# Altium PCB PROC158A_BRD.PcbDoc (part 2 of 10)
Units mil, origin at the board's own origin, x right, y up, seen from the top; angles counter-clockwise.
Board outline 3346.45 x 4921.26 mil, 8 copper layers (Top Layer, GND1, SIG1, PWR1, PWR2, SIG2, GND2, Bottom Layer), stack 54.534 mil thick; 718 components, 459 nets, 2307 pads, 1179 vias.
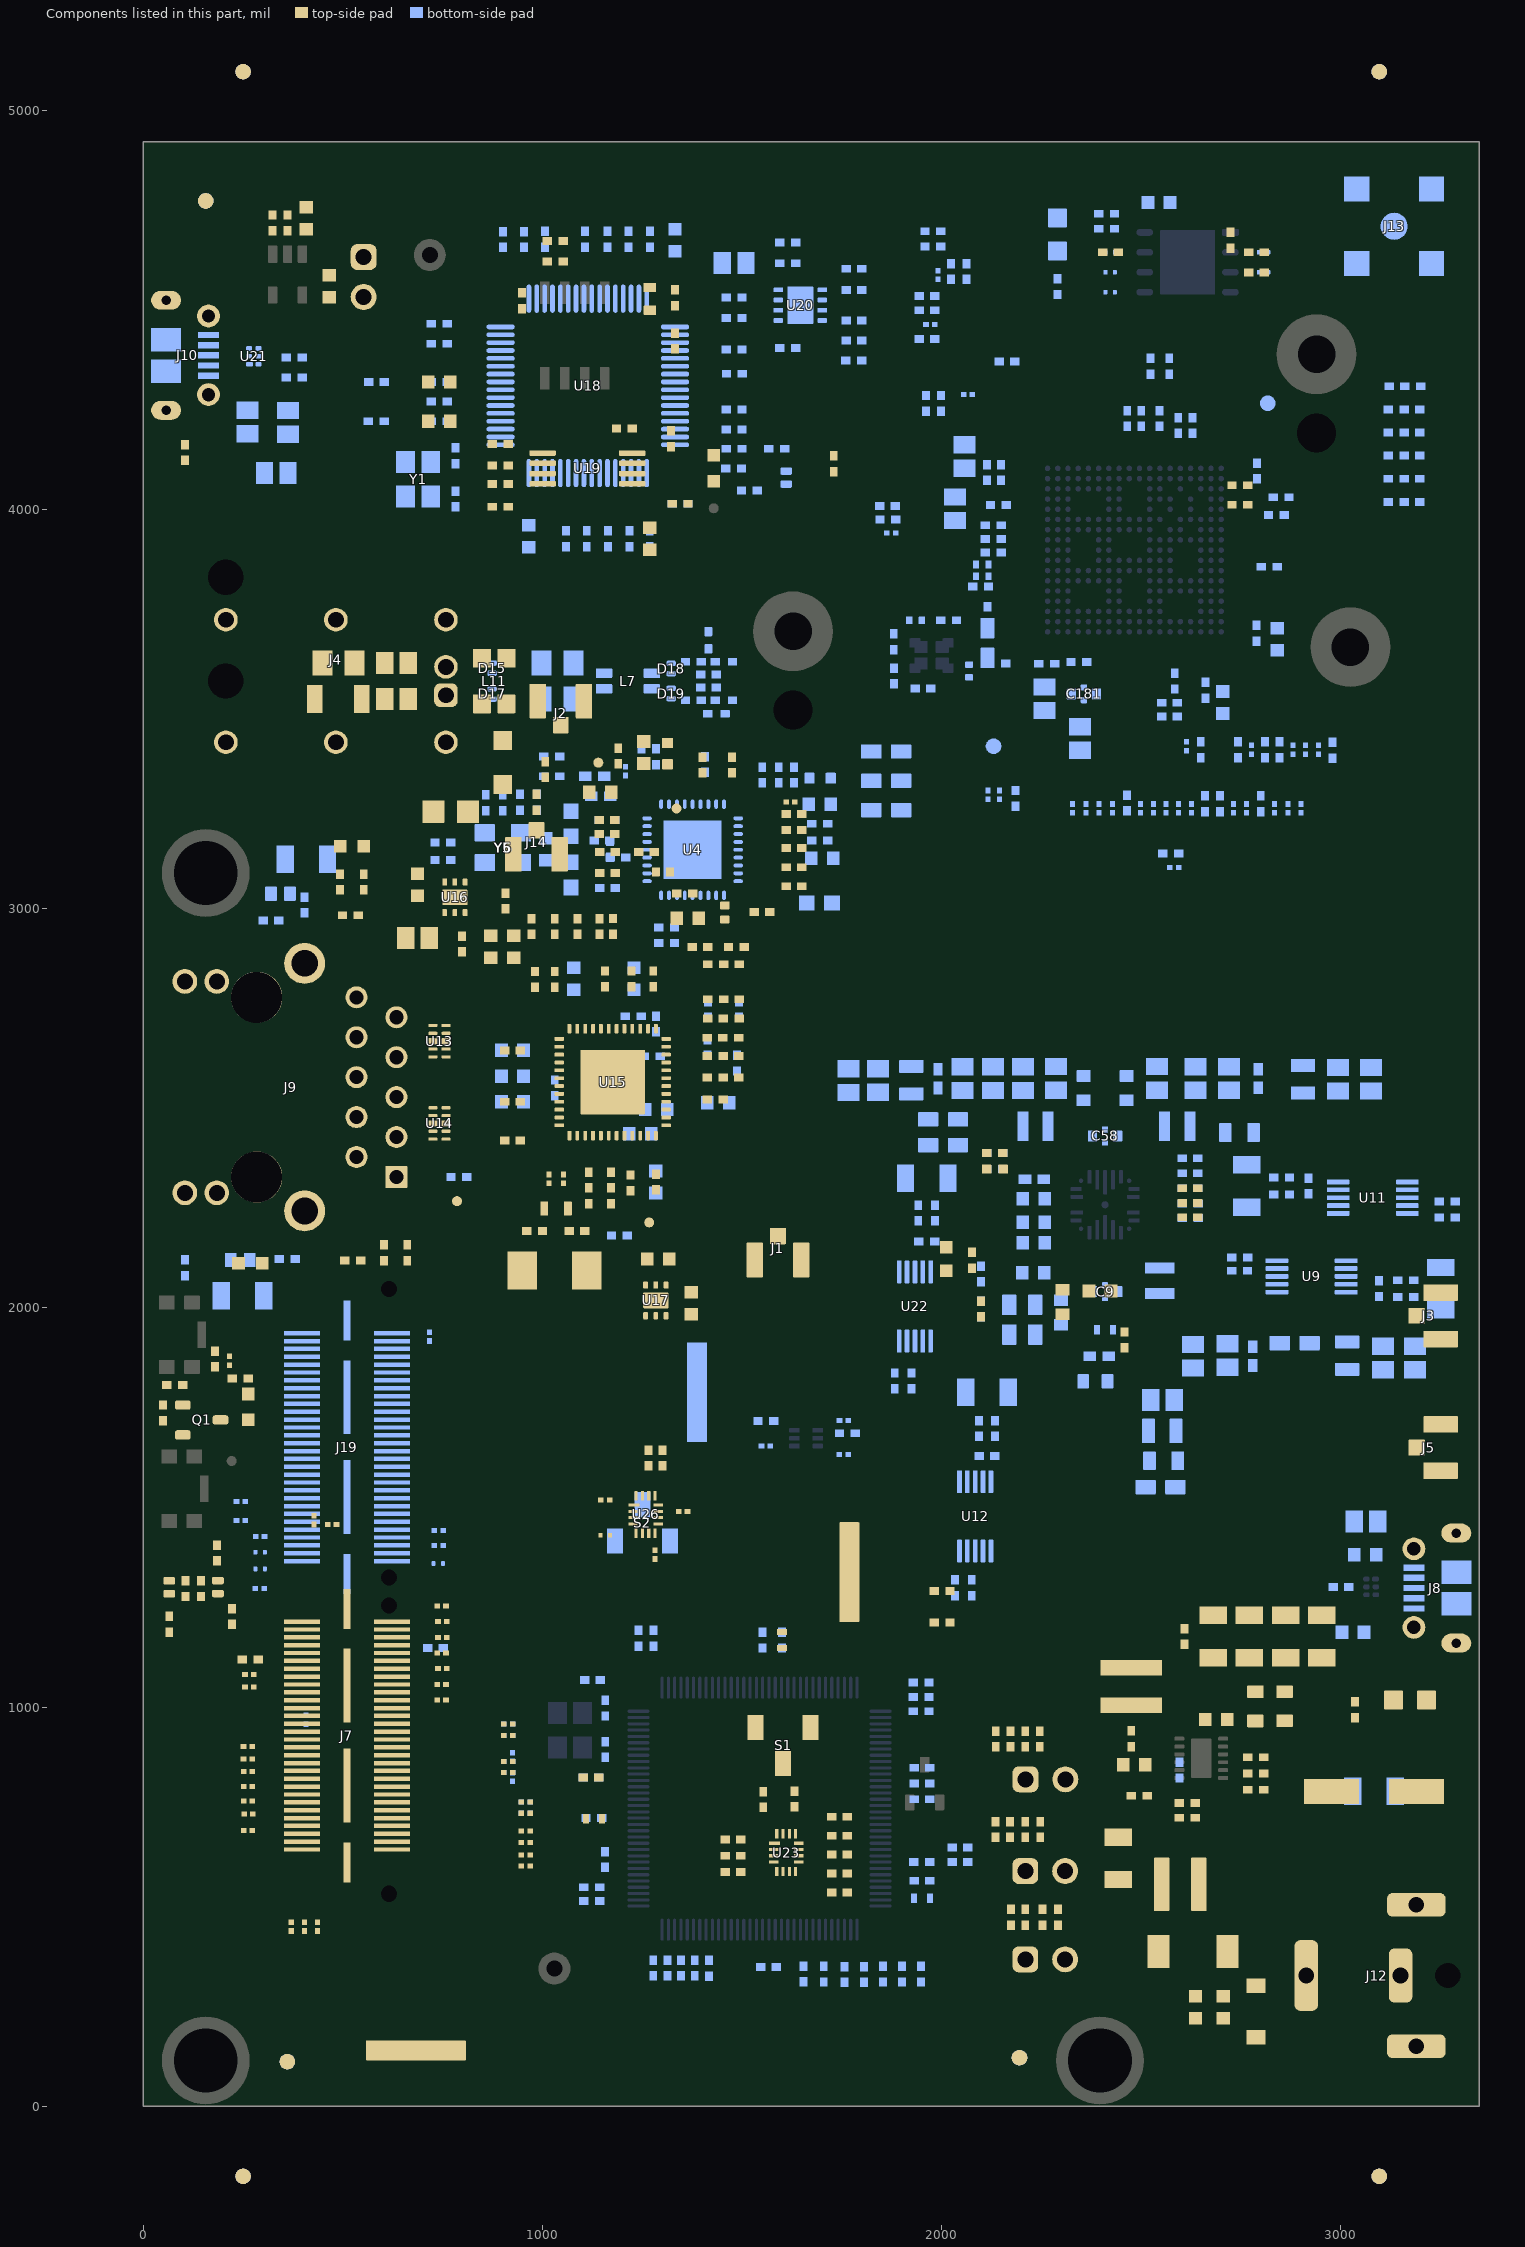
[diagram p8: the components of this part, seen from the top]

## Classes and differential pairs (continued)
component class PROC158A_JTAG_EMU_Connector: C98 J19 R72 R196 R226 R243 R244 R296 R321 R353 R354 R355 R356 R357 R358 R359 R360 R374 R375 R376 R503 R508 R512 S1 U23
component class PROC158A_Auto_Ethernet_PHY: C8 C11 C12 C13 C16 C20 C24 C32 C35 C36 C37 C40 C44 C46 C52 C54 C95 C121 C172 D10 D14 FB1 FB2 FB3 R6 R11 R12 R13 R15 R16 R34 R46 R50 R61 R63 R74 R75 R76 R77 R78 R79 R88 R89 R93 R96 R100 R168 R176 R177 R178 R185 R186 R225 R230 R234 R237 R238 R239 R240 R241 R242 R245 R246 R247 R248 R249 R251 R252 R253 R254 R255 R256 R257 R258 R350 TP2 TP3 U4 Y5 Y6
component class PROC158A_FTDI: C68 C69 C72 C73 C77 C78 C79 C82 C83 C84 C86 C87 C88 C89 C90 C91 D1 L3 L4 R131 R144 R145 R146 R147 R148 R149 R150 R151 R153 R157 R158 R162 R163 R166 R169 R170 R171 R179 R180 R181 R184 R187 R201 R205 R330 U18 U19 Y1
component class PROC158A_FTDI_PWR: C39 C85 C93 C94 C97 J10 R73 R182 R183 R202 R203 R204 R206 R207 R208 R209 U20 U21
component class PROC158A_Ethernet_PWR: C34 C38 C48 C53 C56 C57 C59 C60 C65 C158 C159 C160 C183 C184 C185 C186 C187 C188 C189 C190 C191 C192 C193 R293 R294 R295 U16 U17
component class PROC158A_Ethernet_PHY: C30 C33 D7 D8 m R92 R97 R98 R101 R103 R105 R108 R112 R113 R117 R118 R120 R121 R122 R132 R137 R139 R141 R142 R143 R173 R195 R211 R286 R287 R288 R289 R290 R325 R336 R337 R338 R339 R340 R342 R344 R369 R370 R413 R414 TP5 U15 Y4
component class PROC158A_Ethernet_Magnetics: C27 C28 J9 R68 R69 R119 R130 R400 R401 R419 TP6 U13 U14
component class PROC158A_Debug_Connector: C18 J7 R5 R51 R80 R81 R82 R84 R90 R91 R94 R114 R115 R135 R138 R160 R164 R167 R188 R197 R198 R215 R223 R283 R320 R322 R323 R324 R327 R328 R329 R341 R345 R349 R351 R361 R363 R364 R365 R366 R371 R377 R379 R390 R391 R399 R418 R422 R423 R424 R425 S2 U26
component class PROC158A_Current_Sensors: C14 C17 C19 C81 R26 R27 R29 R30 R32 R33 R35 R47 R56 R57 R58 R59 R60 R62 R64 R65 R66 R346 R348 R352 U9 U11 U12 U22
component class Header: J17 J18 J20 J21 J22 J23 P1
component class Logo: Logo1
component class PROC158A_Hardware: "CAUTION HOT SURFACE1" "ESD Susceptible1" FID1 FID2 FID3 FID4 FID5 FID6 FID7 FID8 FID9 FID10 FID11 FID12 FID13 FID14 FID15 FID16 LBL1 Logo1 LOGO2 Logo3 Logo4 Logo5 ZZ1 ZZ2 ZZ3 ZZ4
component class FiducialMark: FID1 FID2 FID3 FID4 FID5 FID6 FID7 FID8 FID9 FID10 FID11 FID12 FID13 FID14 FID15 FID16
component class AssemblyNote: ZZ1 ZZ2 ZZ3 ZZ4
component class Label: LBL1
differential pair TX4: +TX4_P -TX4_N
differential pair TX2_CLK: +TX2_CLK_P -TX2_CLK_N
differential pair CSI2_TX4_LVDS_CLK: +CSI2_TX4_LVDS_CLK_P -CSI2_TX4_LVDS_CLK_N
differential pair CSI2_TX2_CLK_LVDS_FRCLK: +CSI2_TX2_CLK_LVDS_FRCLK_P -CSI2_TX2_CLK_LVDS_FRCLK_N
differential pair FRCLK: +FRCLK_P -FRCLK_N
differential pair CSI2_TX3: +CSI2_TX3_P -CSI2_TX3_N
differential pair CSI2_TX1_LVDS_TX1: +CSI2_TX1_LVDS_TX1_P -CSI2_TX1_LVDS_TX1_N
differential pair CSI2_TX0_LVDS_TX0: +CSI2_TX0_LVDS_TX0_P -CSI2_TX0_LVDS_TX0_N
differential pair TX3: +TX3_P -TX3_N
differential pair TX1: +TX1_P -TX1_N
differential pair TX0: +TX0_P -TX0_N
differential pair TRD3: +TRD3_P -TRD3_N
differential pair TRD2: +TRD2_P -TRD2_N
differential pair TRD1: +TRD1_P -TRD1_N
differential pair ETH_TRD: +ETH_TRD_P -ETH_TRD_N
differential pair FTDI_USBD: +FTDI_USBD_P -FTDI_USBD_N
differential pair XDSET_1_D: +XDSET_1_D_P -XDSET_1_D_N
differential pair ETH_TD_4: +TD_4_P -TD_4_N
differential pair ETH_TD_3: +TD_3_P -TD_3_N
differential pair ETH_TD_2: +TD_2_P -TD_2_N
differential pair ETH_TD_1: +TD_1_P -TD_1_N

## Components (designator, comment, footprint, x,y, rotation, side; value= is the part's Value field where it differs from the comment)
C1 "GCM188R71C105KA64D" 0603L 2544.56,4769 r180 bottom value=1uF
C2 "CGA2B3X7R1H104K050BB" 0402L 2413.32,4741 r0 bottom value=0.1uF
C3 "GCM188R70J225KE22D" 0603L 2230.57,2273.47 r0 bottom value=2.2uF
C4 "C0805C106J8RACAUTO" 0805L 1840.13,2569.34 r90 bottom value=10uF
C5 "GCM155R71C224KE02D" 0402L 2149,4092.84 r270 bottom value=0.22uF
C6 "GCJ188C70J475KE02J" FP-GCJ188C70J475KE02J_0603-MFG 2385.11,1816.11 r0 bottom value=4.7µF
C7 "GCM21BR71A106KE22L" 0805L 2540,2575 r90 bottom value=10uF
C8 "GCM188R70J225KE22D" 0603L 1694.56,3261.81 r180 bottom value=2.2uF
C9 "NFM18HC105C1C3D" FP-NFM18HC105C1C3D_0603-MFG 2409.48,2040.61 r180 bottom
C10 "GCM188R71C105KA64D" 0603L 2481.98,855.36 r180 top value=1uF
C11 "GCM188R70J225KE22D" 0603L 1144.56,3292 r180 top value=2.2uF
C12 "GCM155R71C104KA55D" 0402L 1023.32,3380.81 r0 bottom value=0.1uF
C13 "GCM155R71C104KA55D" 0402L 1630,3334.81 r270 bottom value=0.1uF
C14 "GCM155R71A104KA55D" 0402L 3095.21,2048.23 r90 bottom value=0.1uF
C15 "GCM21BR71A106KE22L" 0805L 2286,2575 r90 bottom value=10uF
C16 "CGA2B3X7R1H103K050BB" 0402L 1023.32,3331.81 r180 bottom value=0.01uF
C17 "GCM155R71A104KA55D" 0402L 2919.04,2305.44 r270 bottom value=0.1uF
C18 "C0402C104K8RACTU" 0402L 1266.05,1623.71 r270 top value=0.1uF
C19 "GCM155R71A104KA55D" 0402L 2113.62,1628.99 r180 bottom value=0.1uF
C20 "CGA2B3X7R1H103K050BB" 0402L 1592,3334.81 r90 bottom value=0.01uF
C21 "GCM155R71C224KE02D" 0402L 2475,920.74 r90 top value=0.22uF
C22 "GCM155R71C224KE02D" 0402L 2608.2,1176.7 r90 top value=0.22uF
C23 "GCM31CR71A226KE02L" 1206_180L 2952,1176.7 r270 top value=22uF
C24 "GCM188R70J225KE22D" 0603L 1254,3391.25 r270 top value=2.2uF
C25 "GCM31CR71A226KE02L" 1206_180L 2770.83,1176.7 r270 top value=22uF
C26 "GCM31CR71A226KE02L" 1206_180L 2861.42,1176.7 r270 top value=22uF
C27 "C0603C104K4RACAUTO" FP-C0603C104K4RACAUTO_0603-MFG 243.02,2119.9 r0 bottom
C28 "C0603C104K4RACAUTO" FP-C0603C104K4RACAUTO_0603-MFG 343.71,3037.47 r0 bottom
C29 "GCM31CR71A226KE02L" 1206_180L 2680.25,1176.7 r270 top value=22uF
C30 "GCM1555C1H270JA16D" 0402L 1086.42,2192.39 r0 top value=27pF
C31 "GCM21BR71A106KE22L" 0805L 2553.15,1769.45 r0 bottom value=10uF
C32 "GCM188R70J225KE22D" 0603L 1364.39,2976.15 r180 top value=2.2uF
C33 "GCM1555C1H270JA16D" 0402L 980.44,2192.39 r180 top value=27pF
C34 "GCM155R71H102KA37D" 0402L 798.3,2911.52 r90 top value=1000pF
C35 "GCM188R70J225KE22D" 0603L 1700.79,3125.98 r180 bottom value=2.2uF
C36 "GCM155R71C104KA55D" 0402L 1694.5,3171.06 r180 bottom value=0.1uF
C37 "CGA2B3X7R1H103K050BB" 0402L 1311.02,2952.76 r180 bottom value=0.01uF
C38 "CGA4J3X7R1H225K125AB" 0805L 687.02,2927.1 r180 top value=2.2uF
C39 "CL21B106KOQNNNE" 0805L 333.24,4091.18 r180 bottom value=10uF
C40 "GRM155R71E473KA88D" 0402 1146.38,3281.81 r180 bottom value=0.047uF
C41 "GCM155C71A105KE38D" 0402_070 1951,520.81 r0 bottom value=1uF
C42 "C0402C104K8RACTU" 0402L 1128.69,722.02 r0 bottom value=0.1uF
C43 "C0402C104K8RACTU" 0402L 1551.66,1167.61 r270 bottom value=0.1uF
C44 "CGA2B3X7R1H103K050BB" 0402L 1694.5,3212.75 r0 bottom value=0.01uF
C45 "CL21B106KOQNNNE" 0805L 3062.92,1465.35 r0 bottom value=10uF
C46 "GCM155R71C104KA55D" 0402L 1311.02,2914.18 r0 bottom value=0.1uF
C47 "C0402C104K8RACTU" 0402L 949.01,4522.91 r90 top value=0.1uF
C48 "GCM188R71C105KA64D" 0603L 687.02,3059.84 r270 top value=1uF
C49 "C0402C104K8RACTU" 0402L 1123.53,548.54 r180 bottom value=0.1uF
C50 "C0402C103K4RACTU" 0402L 1566.45,349.16 r180 bottom value=0.01uF
C51 "GCM188R70J225KE22D" 0603L 2396.65,2042.31 r180 top value=2.2uF
C52 "CGA2B3X7R1H103K050BB" 0402L 1284.68,3380.79 r90 bottom value=0.01uF
C53 "GCM188R71C105KA64D" 0603L 1229.16,2824.15 r90 bottom value=1uF
C54 "GCM155R71C104KA55D" 0402L 1248.1,3380.79 r270 bottom value=0.1uF
C55 "GCM155R71C224KE02D" 0402L 2097.72,3807.08 r0 bottom value=0.22uF
C56 "GCM188R71C105KA64D" 0603L 925.03,2580.19 r180 bottom value=1uF
C57 "GCM155R71A104KA55D" 0402L 1030.83,2551.1 r270 bottom value=0.1uF
C58 "NFM18HC105C1C3D" FP-NFM18HC105C1C3D_0603-MFG 2409.48,2430.63 r180 bottom
C59 "GCM188R71C105KA64D" 0603L 925.03,2516.33 r180 bottom value=1uF
C60 "GCM188R71C105KA64D" 0603L 1373.01,2012.02 r90 top value=1uF
C61 "GCM155C71A105KE38D" 0402_070 1129.01,720.62 r180 top value=1uF
C62 "GCM155C71A105KE38D" 0402_070 1600.04,1167.93 r90 top value=1uF
C63 "GCM1555C1H8R0DA16D" 0402L 1157.31,997.36 r270 bottom
C64 "C0402C104K8RACTU" 0402L 1600.44,1167.61 r270 bottom value=0.1uF
C65 "GCM188R71C105KA64D" 0603L 1290.01,2122.43 r180 top value=1uF
C66 "C0402C103K4RACTU" 0402L 1950.58,848.1 r180 bottom value=0.01uF
C67 "C0402C104K8RACTU" 0402L 1950.58,808.77 r180 bottom value=0.1uF
C68 "C1608X7S1A475K080AC" 0603L 741.44,4221.1 r180 top value=4.7uF
C69 "C0402C104K8RACTU" 0402L 741.44,4221.1 r0 bottom value=0.1uF
C70 "GCM1555C1H8R0DA16D" 0402L 1157.31,893.56 r270 bottom
C71 "C0402C104K8RACTU" 0402L 1240.63,1172.52 r270 bottom value=0.1uF
C72 "C1608X7S1A475K080AC" 0603L 741.44,4319.53 r180 top value=4.7uF
C73 "C0402C104K8RACTU" 0402L 741.44,4319.53 r0 bottom value=0.1uF
C74 "C1005X7S1A225K050BC" 0402_065L 1121.58,823.24 r0 top value=2.2uF
C75 "C0402C104K8RACTU" 0402L 1121.58,823.24 r0 bottom value=0.1uF
C76 "C0402C104K8RACTU" 0402L 1950.94,564.81 r180 bottom value=0.1uF
C77 "C0402C104K8RACTU" 0402L 1345,4014.41 r0 bottom value=0.1uF
C78 "C0402C104K8RACTU" 0402L 1345,4014.41 r0 top value=0.1uF
C79 "C1608X7S1A475K080AC" 0603L 965.97,3932.47 r270 bottom value=4.7uF
C80 "GCJ188C70J475KE02J" FP-GCJ188C70J475KE02J_0603-MFG 2303.15,2014.75 r90 top value=4.7µF
C81 "GCM155R71A104KA55D" 0402L 1962.59,2166.46 r180 bottom value=0.1uF
C82 "C0402C104K8RACTU" 0402L 1480.12,4400.69 r0 bottom value=0.1uF
C83 "GCM1555C1H8R0DA16D" 0402L 782.36,4134.49 r90 bottom
C84 "GCM1555C1H8R0DA16D" 0402L 782.36,4026.22 r270 bottom
C85 "C1005X7S1A225K050BC" 0402_065L 1614.4,4404.56 r0 bottom value=2.2uF
C86 "C0402C104K8RACTU" 0402L 1205.15,4202.72 r180 top value=0.1uF
C87 "GCM188R71C105KA64D" 0603L 1332.18,4674.04 r90 bottom value=1uF
C88 "C0402C104K8RACTU" 0402L 1269.17,4677.01 r90 bottom value=0.1uF
C89 "C0402C104K8RACTU" 0402L 1480.12,4250.39 r0 bottom value=0.1uF
C90 "GCM188R71C105KA64D" 0603L 1268.76,3926.57 r270 top value=1uF
C91 "C0402C104K8RACTU" 0402L 1268.76,3926.57 r270 bottom value=0.1uF
C92 "GCM155R71C224KE02D" 0402L 2592.82,4210.19 r270 bottom value=0.22uF
C93 "04025A150FAT2A" 0402L 1614.4,4617.01 r0 bottom value=15pF
C94 "C1005X7S1A225K050BC" 0402_065L 1614.4,4668.86 r0 bottom value=2.2uF
C95 "CGA3E2C0G1H220J080AA" 0603 1072,3084.81 r270 bottom value=22pF
C96 "GCM155R71C224KE02D" 0402L 2789,3690 r90 bottom value=0.22uF
C97 "C0402C104K8RACTU" 0402L 378.25,4330.82 r0 bottom value=0.1uF
C98 "C0402C104K8RACTU" 0402L 1631.35,769.51 r270 top value=0.1uF
C99 "EEHZC1V680XP" SM_RADIAL_6.3BMM 3082.94,788.8 r0 top value=68uF
C100 "C3216X7R1H475K160AC" 1206_180L 2442,621 r90 top value=4.7uF
C101 "C3216X7R1H475K160AC" 1206_180L 3082.94,788.8 r0 bottom value=4.7uF
C102 "GRT155R70J105KE01D" FP-GRT155R70J105KE01D_0402-MFG 2101.66,3862.19 r180 bottom
C103 "GRT155R70J105KE01D" FP-GRT155R70J105KE01D_0402-MFG 2101.66,3832.66 r180 bottom
C104 "CGA3E3X8R1H104K080AB" 0603L 2705.05,248.05 r270 top value=0.1uF
C105 "GCM155R71C104KA55D" 0402L 105.96,1296.65 r90 top value=0.1uF
C106 "GCM1555C1H3R9BA16D" FP-GCM1555C1H3R9BA16D_0402-MFG 1934.63,3722.51 r180 bottom value=3.9pF
C107 "GCM155R71C224KE02D" 0402L 2129.27,3960.48 r0 bottom value=0.22uF
C108 "GCM1555C1H3R9BA16D" FP-GCM1555C1H3R9BA16D_0402-MFG 2068.85,3595.44 r270 bottom value=3.9pF
C109 "C0402C103K4RACTU" 0402L 1948.63,1025.56 r180 bottom value=0.01uF
C110 "GCM21BR71A106KE22L" 0805L 2257.86,3525.98 r270 bottom value=10uF
C111 "GCM155R71C224KE02D" 0402L 2129.27,3892.34 r0 bottom value=0.22uF
C112 "GCM21BR71A106KE22L" 0805L 2057,4132.53 r90 bottom value=10uF
C113 "GCM155R71C224KE02D" 0402L 2114,4092.84 r270 bottom value=0.22uF
C114 "GCM21BR71A106KE22L" 0805L 2033.6,4001.8 r270 bottom value=10uF
C115 "GCM155R71C224KE02D" 0402L 2142.12,4011.14 r0 bottom value=0.22uF
C116 "GCM21BR71A106KE22L" 0805L 2347,3426.47 r270 bottom value=10uF
C117 "GCM155R71C224KE02D" 0402L 2343.69,3618 r180 bottom value=0.22uF
C118 "CGA4J1X7R1H475K125AC" FP-CGA4J1X7R1H475K125AC_0805-MFG 2786.07,1001.58 r270 top value=4.7µF
C119 "GCM155R71C224KE02D" 0402 2793.46,2574.68 r90 bottom value=0.22uF
C120 "GCM155R71C224KE02D" 0402 1990.96,2574.38 r90 bottom value=0.22uF
C121 "CGA3E2C0G1H220J080AA" 0603 1071.93,3212.81 r90 bottom value=22pF
C122 "GCM155R71C224KE02D" 0402 2779.53,1879.19 r270 bottom value=0.22uF
C123 "GCM188R70J225KE22D" 0603L 2230.89,2214.34 r0 bottom value=2.2uF
C124 "GCM21BR71A106KE22L" 0805L 2203.5,2574.34 r90 bottom value=10uF
C125 "GCM21BR71A106KE22L" 0805L 2719.81,2574.81 r90 bottom value=10uF
C126 "CGA3E3X8R1H104K080AB" 0603L 2635.95,248.44 r270 top value=0.1uF
C127 "GCM21BR71A106KE22L" 0805L 2635.32,2574.81 r90 bottom value=10uF
C128 "CGA4J1X7T0J226M" 0805_155 3015.86,1880.36 r270 bottom value=22uF
C129 "GCM21BR71A106KE22L" 0805L 2715.81,1880.94 r270 bottom value=10uF
C130 "GCM21BR71A106KE22L" 0805L 2629.81,1878.94 r270 bottom value=10uF
C131 "GCM155R71C104KA55D" 0402L 1998.62,4265.88 r90 bottom value=0.1uF
C132 "GCM21BR71A106KE22L" 0805L 2052.83,2574.34 r90 bottom value=10uF
C133 "C0402C104K8RACTU" 0402L 1763.74,1685.81 r0 bottom value=0.1uF
C134 "GCM21BR71A106KE22L" 0805L 2128.17,2574.34 r90 bottom value=10uF
C135 "GCM155R71C104KA55D" 0402L 1865.22,3974.81 r0 bottom value=0.1uF
C136 "GCM155R71C104KA55D" 0402L 2062.61,4596.13 r270 bottom value=0.1uF
C137 "GCM188R70J225KE22D" 0603L 2704,3516.44 r90 bottom value=2.2uF
C138 "GCM155R71C224KE02D" 0402L 2747,4012 r180 top value=0.22uF
C139 "GCM155R71C224KE02D" 0402L 2661,3547.32 r90 bottom value=0.22uF
C140 "GCM155R71C224KE02D" 0402L 2464.86,4228.19 r270 bottom value=0.22uF
C141 "GCM155R71C224KE02D" 0402L 2628.47,4210.19 r270 bottom value=0.22uF
C142 "GCM155R71C224KE02D" 0402L 2747,4060.87 r180 top value=0.22uF
C143 "CGA4J1X7T0J226M" 0805_155 2552.66,1692.06 r0 bottom value=22uF
C144 "GCJ188C70J475KE02J" FP-GCJ188C70J475KE02J_0603-MFG 2463.29,2550.43 r270 bottom value=4.7µF
C145 "GCM188R71C105KA64D" 0603L 408.44,4729.82 r90 top value=1uF
C146 "GCM188R70J225KE22D" 0603L 2841,3675.44 r90 bottom value=2.2uF
C147 "GCJ188C70J475KE02J" FP-GCJ188C70J475KE02J_0603-MFG 2299.36,1988.38 r90 bottom value=4.7µF
C148 "GCM188R70J225KE22D" 0603L 2230.89,2163.42 r0 bottom value=2.2uF
C149 "GCM188R70J225KE22D" 0603L 466.12,4559.69 r270 top value=2.2uF
C150 "GCM155R71C104KA55D" 0402L 2838.54,3986.51 r180 bottom value=0.1uF
C151 "CGA4J1X7T0J226M" 0805_155 1924.06,2570.34 r90 bottom value=22uF
C152 "C0805C106J8RACAUTO" 0805L 1767,2569.26 r90 bottom value=10uF
C153 "GCJ188C70J475KE02J" FP-GCJ188C70J475KE02J_0603-MFG 2355.67,2550.43 r270 bottom value=4.7µF
C154 "C0805C106J8RACAUTO" 0805L 3105.86,1874.28 r270 bottom value=10uF
C155 "KGM05ACG1H470FH" FP-KGM05ACG1H470FH_0402-MFG 1415.62,3672.6 r270 bottom value=47pF
C156 "KGM05ACG1H220FH" FP-KGM05ACG1H220FH_0402-MFG 1454.38,3618.51 r0 bottom value=22pF
C157 "CGA4J2X7R2A104K125AA" 0805_HV 1037.67,3615.54 r0 bottom value=0.1uF
C158 "GCM155R71A104KA55D" 0402L 1432.69,2522.05 r0 top value=0.1uF
C159 "GCM188R71C105KA64D" 0603L 1078.54,2824.03 r90 bottom value=1uF
C160 "GCM155R71A104KA55D" 0402L 1156.91,2824.15 r90 top value=0.1uF
C161 "CGA4J2X7R2A104K125AA" 0805_HV 1037.67,3524.99 r0 bottom value=0.1uF
C162 "KGM05ACG1H220FH" FP-KGM05ACG1H220FH_0402-MFG 1454.38,3522.02 r180 bottom value=22pF
C163 "GCM155R71C224KE02D" 0402L 2500.01,4228.19 r270 bottom value=0.22uF
C164 "GCM155R71C224KE02D" 0402L 2584,3570 r90 bottom value=0.22uF
C165 "GCM155R71C224KE02D" 0402L 2789.81,4096.45 r270 bottom value=0.22uF
C166 "KGM05ACG1H470FH" FP-KGM05ACG1H470FH_0402-MFG 1435.86,3488.17 r0 bottom value=47pF
C167 "CC1206KKX7RCBB472" FP-CC1206KKX7RCBB472_1206-MFG 488.5,3525.09 r180 top value=4.7nF
C168 "GCM155R71C224KE02D" 0402L 2263.21,3613.51 r0 bottom value=0.22uF
C169 "CGA4J1X7T0J226M" 0805_155 2905.34,2572.81 r90 bottom value=22uF
C170 "GCM155R71C224KE02D" 0402L 2820.54,3856.66 r180 bottom value=0.22uF
C171 "GCM188R70J225KE22D" 0603L 2230,2088 r0 bottom value=2.2uF
C172 "GCM155R71C104KA55D" 0402L 750.45,3166.22 r0 bottom value=0.1uF
C173 "CGA4J1X7R1H475K125AC" FP-CGA4J1X7R1H475K125AC_0805-MFG 2859,1001.72 r270 top value=4.7µF
C174 "GCM155R71C224KE02D" 0402L 2850.54,4030.51 r180 bottom value=0.22uF
C175 "GCM155R71C224KE02D" 0402L 2571,3481.13 r180 bottom value=0.22uF
C176 "GCM155R71C224KE02D" 0402L 2546.16,4228.19 r270 bottom value=0.22uF
C177 "GCM155R71C224KE02D" 0402L 2571,3516 r180 bottom value=0.22uF
C178 "GCM155R71C104KA55D" 0402L 1880.27,3582.64 r90 bottom value=0.1uF
C180 "CGA2B3X7R1H473K050BB" 0402L 2129.27,3926.41 r180 bottom value=0.047uF
C181 "NFM18HC105C1C3D" FP-NFM18HC105C1C3D_0603-MFG 2356.32,3538.13 r180 bottom
C182 "C0805C106J8RACAUTO" 0805L 3185.45,1874.28 r270 bottom value=10uF
C183 "GCM188R71C105KA64D" 0603L 1245.36,2436.07 r0 bottom value=1uF
C184 "GCM155R71A104KA55D" 0402L 1220.92,2313.15 r270 top value=0.1uF
C185 "GCM155R71A104KA55D" 0402L 1223.16,2824.15 r90 top value=0.1uF
C186 "GCM188R71C105KA64D" 0603L 1440.59,2513.53 r0 bottom value=1uF
C187 "GCM188R71C105KA64D" 0603L 925.03,2645.15 r180 bottom value=1uF
C188 "GCM155R71A104KA55D" 0402L 925.03,2516.33 r180 top value=0.1uF
C189 "GCM155R71A104KA55D" 0402L 925.03,2645.15 r180 top value=0.1uF
C190 "GCM188R71C105KA64D" 0603L 1284.2,2315.32 r270 bottom value=1uF
C191 "GCM155R71A104KA55D" 0402L 1284.2,2315.32 r270 top value=0.1uF
C192 "GCM188R71C105KA64D" 0603L 1285.02,2497.07 r180 bottom value=1uF
C193 "GCM155R71A104KA55D" 0402L 1275.32,2630.46 r180 bottom value=0.1uF
C194 "C0805C106J8RACAUTO" 0805L 2992.4,2572.81 r90 bottom value=10uF
C195 "CGA3E3X7R1H224K080AB" 0603L 2687.59,968.72 r180 top value=0.22uF
C198 "C0805C106J8RACAUTO" 0805L 3075.34,2572.81 r90 bottom value=10uF
C199 "GCM155R71C224KE02D" 0402 2394.95,1879.11 r180 bottom value=0.22uF
C200 "GCM155R71C104KA55D" 0402S 2409.48,1945.25 r0 bottom value=0.1uF
"CAUTION HOT SURFACE1" "CAUTION HOT SURFACE" IEC_HotSurface_Small 2645.54,2047.06 r0 top
D1 "TLMY1000-GS08" TLMx1000_Yellow 1269.17,4527.56 r270 top value=Yellow
D2 "SMS3923-040LF" SOD-882 187,1300.57 r90 top value=V
D3 "ATV02W280B-HF" SOD-123 2787.46,237.64 r90 top value=28V
D4 "SMS3923-040LF" SOD-882 64.98,1300.09 r90 top value=V
D5 "SMS3923-040LF" SOD-882 1610.48,4079.94 r270 bottom value=V
D6 "SML-LXT0805GW-TR" SML_Green_0805 2290,4689 r90 bottom value=Green
D7 "LS L29K-G1J2-1-Z" "LS L29K_Red" 522.64,3156.33 r180 top value=Red
D8 "LS L29K-G1J2-1-Z" "LS L29K_Red" 268.02,2111.43 r180 top value=Red
D9 "SML-E12Y8WT86" SML-E1_Yellow 1429.01,4103.13 r90 top value=Yellow
D10 "SML-P12YTT86R" FP-SML-P12YTT86R_0402-MFG 1456.84,2990.67 r90 top
D11 "PMEG3050EP,115" SOD-128 2629.8,387.81 r0 top value=30V
D12 "SML-LXT0805GW-TR" SML_Green_0805 3173.34,1017.81 r0 top value=Green
D13 "SML-E12Y8WT86" SML-E1_Yellow 262.47,1751.71 r90 top value=Yellow
D14 "SML-P12DTT86R" FP-SML-P12DTT86R_0402-MFG 1301.91,3091.95 r180 top
D15 "TPD1E05U06QDPYRQ1" DPY0002A 873.77,3602.58 r90 bottom
D16 "PMEG6020ER,115" SOD-123W 900.51,3366.46 r90 top value=60V
D17 "TPD1E05U06QDPYRQ1" DPY0002A 873.77,3537.94 r270 bottom
D18 "TPD1E05U06QDPYRQ1" DPY0002A 1322.29,3601.54 r90 bottom
D19 "TPD1E05U06QDPYRQ1" DPY0002A 1322.29,3538.98 r270 bottom
Designator9 "Comment" VGROVE_1-6_45A 9544.57,4519.72 r0 top
DS2 "LS L29K-G1J2-1-Z" "LS L29K_Red" 2011.69,2122.43 r90 top value=Red
"ESD Susceptible1" "ESD Susceptible" ESD_Overlay_Small 1175.93,1141.93 r0 top
FB1 "BLM18HE102SN1D" 0603 1693.87,3013.81 r180 bottom value="1000 ohm"
FB2 "BLM18KG601SH1" "FP-BLM18KG601SH1_0603 (1608 Metric)-MFG" 1695.58,3326.81 r180 bottom
FB3 "BLM18KG601SH1" "FP-BLM18KG601SH1_0603 (1608 Metric)-MFG" 1313,3388.39 r270 top
FID1 "Fiducial" Fiducial10-20 2130,3407 r90 bottom
FID2 "Fiducial" Fiducial10-20 2817,4266 r90 bottom
FID3 "Fiducial" Fiducial10-20 361,111.81 r90 top
FID4 "Fiducial" Fiducial10-20 361,111.81 r90 bottom
FID5 "Fiducial" Fiducial10-20 2195,121.81 r90 bottom
FID6 "Fiducial" Fiducial10-20 2195,121.81 r90 top
FID7 "Fiducial" Fiducial10-20 250,5096.84 r90 bottom
FID8 "Fiducial" Fiducial10-20 250,5096.84 r90 top
FID9 "Fiducial" Fiducial10-20 156.55,4772.91 r90 bottom
FID10 "Fiducial" Fiducial10-20 156.55,4772.91 r90 top
FID11 "Fiducial" Fiducial10-20 3096.45,5096.84 r90 bottom
FID12 "Fiducial" Fiducial10-20 250,-175.59 r90 top
FID13 "Fiducial" Fiducial10-20 250,-175.59 r90 bottom
FID14 "Fiducial" Fiducial10-20 3096.45,5096.84 r90 top
FID15 "Fiducial" Fiducial10-20 3096.45,-175.59 r90 bottom
FID16 "Fiducial" Fiducial10-20 3096.45,-175.59 r90 top
J1 "1909763-1" "FP-1909763-1_SMT_JACK _CONN-MFG" 1590,2117.01 r180 top
J2 "128-0711-201" Johnson_128-0711-201 1046,3520 r180 top
J3 "1909763-1" "FP-1909763-1_SMT_JACK _CONN-MFG" 3252.99,1980 r270 top
J4 "9-2304372-9" TE_9-2304372-9 207.07,3570.26 r90 bottom locked
J5 "1909763-1" "FP-1909763-1_SMT_JACK _CONN-MFG" 3252.99,1650 r270 top
J7 "QSH-030-01-L-D-A" Samtec_QSH-030-01-X-D-A 510.29,928.61 r0 top locked
J8 "105017-0001" CONN_105017-0001 3236.22,1298.04 r270 bottom
J9 "LPJG16414A4NL" FP-LPJG16414A4NL_CONN_RJ45-MFG 279.25,2552.93 r90 bottom
J10 "105017-0001" CONN_105017-0001 110.24,4386.21 r90 bottom
J12 "PJ-063AH" CUI_PJ-063AH 3090.58,327.49 r0 bottom locked
J13 "142-0711-201" 142-0711-201 3133.5,4709.5 r180 bottom
J14 "128-0711-201" Johnson_128-0711-201 985,3136.24 r0 top
J17 "TSW-102-07-G-S" TSW-102-07-G-S 2259.53,367.91 r0 top
J18 "TSW-102-07-G-S" TSW-102-07-G-S 2259.53,589.17 r0 top
J19 "Receptacle_30x2_4MP_LeftRight" Samtec_QSH-030-01-X-D-A 510.29,1651.13 r0 bottom
J20 "TSW-102-07-G-S" TSW-102-07-G-S 2259.78,818.98 r0 top
J21 "GBC01SFBN-M30" Sullins_GBC01SFBN-M30 1387,1688.81 r180 bottom
J22 "GBC01SFBN-M30" Sullins_GBC01SFBN-M30 783,139.81 r90 top
J23 "GBC01SFBN-M30" Sullins_GBC01SFBN-M30 1769,1438 r180 top
L1 "MPZ2012S101ATD25" FP-MPZ2012S101ATD25_0805-MFG 2556.1,1617.06 r180 bottom
L2 "VCTA20161B-R47MS6" VCTA20161B 2546.36,2067.88 r270 bottom value=470nH
L3 "BLM15HG601SN1D" 0402L 583.79,4221.1 r0 bottom value="600 ohm"
L4 "BLM15HG601SN1D" 0402L 584.54,4319.53 r0 bottom value="600 ohm"
L5 "XAL4030-472MEC" FP-XAL4030-472MEC_SMD2-MFG 2597.65,555.81 r0 top value=4.7µH
L6 "XEL4030-222MEB" XEL4030_310 2475,1051.58 r90 top value=2.2uH
L7 "DLW32MH101XT2" FP-DLW32MH101XT2_1210-MFG 1214.23,3570.26 r180 bottom
L8 "VCTA20161B-R47MS6" VCTA20161B 2234.78,2455 r180 bottom value=470nH
L9 "VCTA20161B-R47MS6" VCTA20161B 2590.04,2455 r0 bottom value=470nH
L11 "ADL32VHR-3R9M" FP-ADL32VHR-3R9M_SMT_3MM2_2MM5-MFG 879,3570.26 r90 top
L12 "MPZ2012S101ATD25" FP-MPZ2012S101ATD25_0805-MFG 2746,2439.25 r0 bottom
LBL1 "THT-14-423-10" Label_650x200 1753,135 r0 bottom value=xWR2944EVM
Logo1 "Texas Instruments" TI_Stacked_Overlay_Small 505.9,3985.56 r0 top
LOGO2 "CE Mark" CE_Mark_5mm 607.66,1653.96 r90 top
Logo3 "FCC disclaimer" FCC_disclaimer 1703,1363 r90 top
Logo4 "WEEE logo" WEEE_Minimum 1858.14,1086.24 r0 top
Logo5 "UKCA Marking" -UKCA_Filled 997.71,1773.46 r0 top
NT1 "Net-Tie" Net-Tie_50milWide_30milLong 2478.75,2257.31 r180 top net-tie
NT2 "Net-Tie" Net-Tie_50milWide_30milLong 2409.68,2306.89 r90 top net-tie
NT3 "Net-Tie" Net-Tie_50milWide_30milLong 2408.93,2210.5 r270 top net-tie
NT4 "Net-Tie" Net-Tie_50milWide_30milLong 2340.02,2259 r180 top net-tie
P1 "TSW-102-07-G-S" TSW-102-07-G-S 552.17,4582.33 r270 top
Q1 "BSS123" SOT-23 146.25,1719.23 r0 top value=100V
R1 "ERJ-2GE0R00X" 0402L 2494.98,777.76 r180 top value=0
R2 "CRCW04027K50FKED" 0402L 2595.64,842 r90 bottom value=7.50k
R3 "ERJ-2GE0R00X" 0402L 2523,4358.69 r270 bottom value=0
R4 "ERJ-2GE0R00X" 0402L 2786.69,792.81 r180 top value=0
R5 "CRCW02010000Z0ED" 0201L 2582.58,3103 r0 bottom value=0
R6 "ERJ-2GE0R00X" 0402L 2573.92,3138 r180 bottom value=0
R7 "CRCW040210K0FKED" 0402L 2786.69,874.31 r180 top value=10.0k
R8 "CRCW040210K0FKED" 0402L 2786.69,833.56 r0 top value=10.0k
R9 "CRCW040210K0FKED" 0402L 2615.32,722.58 r0 top value=10.0k
R10 "CRCW040210K0FKED" 0402L 2615.32,759.44 r180 top value=10.0k
R11 "CRCW040210K0FKED" 0402L 1161.75,3222.28 r0 bottom value=10.0k
R12 "CRCW02010000Z0ED" 0201L 1208,3344.84 r270 bottom value=0
R13 "CRCW04022K49FKED" 0402L 1162.89,3142.2 r180 top value=2.49k
R14 "ERJ-2GE0R00X" 0402L 2622.41,2374.81 r0 bottom value=0
R15 "CRCW04022K49FKED" 0402L 1356.52,3038.39 r180 top value=2.49k
R16 "CRCW04022K49FKED" 0402L 1630.02,3196.81 r0 top value=2.49k
R17 "CRCW040210K0FKED" 0402L 2979,3396.98 r90 bottom value=10.0k
R18 "CRCW02010000Z0ED" 0201L 1971.98,4463 r0 bottom value=0
R19 "ERJ-2GE0R00X" 0402L 2649.2,3398.33 r270 bottom value=0
R20 "ERJ-2GE0R00X" 0402L 2133.32,2347.81 r180 bottom value=0
R21 "CRCW02010000Z0ED" 0201L 2394.61,3251.25 r270 bottom value=0
R22 "ERJ-2GE0R00X" 0402L 2185,3276.32 r90 bottom value=0
R23 "ERJ-2GE0R00X" 0402L 2799.39,3262.7 r90 bottom value=0
R24 "CRCW02010000Z0ED" 0201L 2427.99,3251.25 r270 bottom value=0
R25 "CRCW02010000Z0ED" 0201L 2530.2,3251.25 r270 bottom value=0
R26 "CRCW040210R2FKED" 0402L 3162.5,2069.26 r180 bottom value=10.2
R27 "ERJ-2GE0R00X" 0402L 2746.84,2125.82 r180 bottom value=0
R28 "ERJ-2GE0R00X" 0402L 2660,3262.7 r270 bottom value=0
R29 "ERJ-2GE0R00X" 0402L 2746.55,2092.89 r180 bottom value=0
R30 "CSNL1206FT1L00" 1206L 3249.98,2048.23 r270 bottom value=0.001
R31 "ERJ-2GE0R00X" 0402L 2570,4358.69 r270 bottom value=0
R32 "CRCW040210R2FKED" 0402L 3162.5,2027.2 r180 bottom value=10.2
R33 "ERJ-2GE0R00X" 0402L 3266.69,2226.39 r0 bottom value=0
R34 "CRCW04022K20JNED" 0402L 1162.88,3052.21 r0 bottom value=2.2k
R35 "ERJ-2GE0R00X" 0402L 3266.69,2266.39 r0 bottom value=0
R36 "CRCW040210R2FKED" 0402L 222,1227.13 r90 top value=10.2
R37 "ERJ-2GE0R00X" 0402L 2413.32,4703.33 r0 bottom value=0
R38 "CRCW040247K5FKED" 0402L 2723.49,4674.65 r270 top value=47.5k
R39 "ERJ-1GNF33R2C" FP-ERJ-1GNF33R2C_0201-MFG 2806.45,4644.33 r180 bottom value=33.2
R40 "ERJ-1GNF33R2C" FP-ERJ-1GNF33R2C_0201-MFG 2422.08,4644.33 r180 bottom value=33.2
R41 "CRCW040210K0FKED" 0402L 2423.09,4644.33 r0 top value=10.0k
R42 "ERJ-1GNF33R2C" FP-ERJ-1GNF33R2C_0201-MFG 2806.45,4594.03 r180 bottom value=33.2
R43 "CRCW040210K0FKED" 0402L 2788.58,4594.03 r180 top value=10.0k
R44 "ERJ-1GNF33R2C" FP-ERJ-1GNF33R2C_0201-MFG 2422.08,4594.33 r180 bottom value=33.2
R45 "ERJ-1GNF33R2C" FP-ERJ-1GNF33R2C_0201-MFG 2422.08,4544.33 r180 bottom value=33.2
R46 "CRCW040210K0FKED" 0402L 1162.88,3088.99 r0 top value=10.0k
R47 "CRCW040210R2FKED" 0402L 2851.74,2284.41 r0 bottom value=10.2
R48 "CRCW04020000Z0EDHP" 0402 2232.38,2321.81 r0 bottom value=0
R49 "CRCW040210K0FKED" 0402L 2788.58,4644.33 r180 top value=10.0k
R50 "ERJ-2GE0R00X" 0402L 1161.75,3222.28 r180 top value=0
R51 "CRCW02010000Z0ED" 0201L 958.02,762 r0 bottom value=0
R52 "CRCW04020000Z0EDHP" 0402L 2622.41,2299.62 r180 top value=0
R53 "CRCW04020000Z0EDHP" 0402L 2622.41,2299.62 r180 bottom value=0
R54 "ERJ-2GE0R00X" 0402L 2133,2387.81 r0 top value=0
R55 "ERJ-2GE0R00X" 0402L 1963.32,4499 r0 bottom value=0
R56 "CRCW040210R2FKED" 0402L 1941.56,2237.73 r270 bottom value=10.2
R57 "ERJ-2GE0R00X" 0402L 1882.53,1817.13 r270 bottom value=0
R58 "ERJ-2GE0R00X" 0402L 2033.57,1298.99 r270 bottom value=0
R59 "ERJ-2GE0R00X" 0402L 2075.57,1298.99 r270 bottom value=0
R60 "CSNL1206FT1L00" 1206L 2764.26,2305.44 r90 bottom value=0.001
R61 "CRCW02010000Z0ED" 0201L 1621.41,3266.81 r0 top value=0
R62 "ERJ-2GE0R00X" 0402L 1924.53,1817.13 r270 bottom value=0
R63 "CRCW04020000Z0EDHP" 0402 1131,3331.81 r0 bottom value=0
R64 "CSNL1206FT1L00" 1206L 1962.59,2325.21 r0 bottom value=0.001
R65 "CRCW040210R2FKED" 0402L 2851.74,2326.47 r0 bottom value=10.2
R66 "CRCW040210R2FKED" 0402L 1983.62,2237.73 r270 bottom value=10.2
R67 "ERJ-2GE0R00X" 0402L 2622.41,2337.21 r0 bottom value=0
R68 "CRCW0402220RJNED" 0402L 104.25,2100.54 r90 bottom value=220
R69 "CRCW0402220RJNED" 0402L 320.09,2970.41 r0 bottom value=220
R70 "ERJ-2GE0R00X" 0402L 2622.69,2260.81 r0 bottom value=0
R71 "ERJ-2GE0R00X" 0402L 2133,2387.81 r180 bottom value=0
R72 "CRCW02010000Z0ED" 0201L 427.98,1468.54 r90 top value=0
R73 "CRCW0402100KFKED" 0402L 1780,4372.81 r0 bottom value=100k
R74 "CRCW040233R2FKED" 0402L 3178.31,4019 r0 bottom value=33.2
R75 "CRCW04022K49FKED" 0402L 1550.61,3334.81 r90 bottom value=2.49k
R76 "ERJ-2GE0R00X" 0402L 750.45,3166.22 r0 bottom value=0
R77 "ERJ-2RKF4700X" 0402L 1550.15,2992 r0 top value=470
R78 "CRCW02010000Z0ED" 0201L 2944,3398.33 r90 bottom value=0
R79 "ERJ-2GE0R00X" 0402L 750.45,3121.72 r0 bottom value=0
R80 "CRCW02010000Z0ED" 0201L 1991.38,4587.47 r90 bottom value=0
R81 "CRCW02010000Z0ED" 0201L 749.22,1214.04 r180 top value=0
R82 "CRCW02010000Z0ED" 0201L 1873.88,3940.97 r180 bottom value=0
R83 "ERJ-2GEJ101X" 0402L 2017.54,3722.51 r180 bottom value=100
R84 "CRCW02010000Z0ED" 0201L 747.25,1253.41 r180 top value=0
R85 "ERJ-2GE0R00X" 0402L 2140.54,3614.51 r180 bottom value=0
R86 "ERJ-2GE0R00X" 0402L 1953.36,3551.94 r180 bottom value=0
R87 "ERJ-2GE0R00X" 0402L 1879.89,3668.62 r270 bottom value=0
R88 "HCJ0603ZT0R00" FP-HCJ0603ZT0R00_0603-MFG 1861,3320.31 r0 bottom value=0
R89 "HCJ0603ZT0R00" FP-HCJ0603ZT0R00_0603-MFG 1861,3393.81 r0 bottom value=0
R90 "CRCW02010000Z0ED" 0201L 747.25,1135.3 r180 top value=0
R91 "CRCW02010000Z0ED" 0201L 408.16,968.36 r270 bottom value=0
R92 "CRCW04022K49FKED" 0402L 972.5,2955.6 r90 top value=2.49k
R93 "ERJ-2RKF4700X" 0402L 1260.51,3142.2 r180 top value=470
R94 "CRCW02010000Z0ED" 0201L 2065.98,4288 r180 bottom value=0
R95 "ERJ-2GE0R00X" 0402L 985,3266.81 r90 top value=0
R96 "CRCW040233R2FKED" 0402L 3180.28,4308.84 r0 bottom value=33.2
R97 "CRCW04022K49FKED" 0402L 981.5,2822.91 r90 top value=2.49k
R98 "CRCW040233R2FKED" 0402L 3138.94,4019 r180 bottom value=33.2
R99 "CRCW04021K00FKED" 0402L 2622.41,2226.96 r180 top value=1.00k
R100 "CRCW040233R2FKED" 0402L 3178.31,4250.87 r0 bottom value=33.2
R101 "CRCW040233R2FKED" 0402L 3138.94,4076.97 r180 bottom value=33.2
R102 "CRCW040210K0FKED" 0402L 2622.41,2262.84 r0 top value=10.0k
R103 "CRCW040233R2FKED" 0402L 3140.91,4308.84 r180 bottom value=33.2
R104 "CRCW02010000Z0ED" 0201L 2867.31,3251.25 r270 bottom value=0
R105 "CRCW040233R2FKED" 0402L 3138.94,4250.87 r180 bottom value=33.2
R106 "CRCW04020000Z0EDHP" 0402L 2099,2085.06 r270 bottom value=0
R107 "HCJ0603ZT0R00" FP-HCJ0603ZT0R00_0603-MFG 2234.36,1970.38 r90 bottom value=0
R108 "ERJ-2RKF4700X" 0402L 552.17,3066.83 r270 top value=470
R109 "HCJ0603ZT0R00" FP-HCJ0603ZT0R00_0603-MFG 2169.36,1970.38 r90 bottom value=0
R110 "HCJ0603ZT0R00" FP-HCJ0603ZT0R00_0603-MFG 2884.26,1911.81 r0 bottom value=0
R111 "CRCW04024K22FKED" FP-CRCW04024K22FKED_0402-MFG 2133.32,2347.81 r0 top value=4.22k
R112 "CRCW04022K49FKED" 0402L 518.7,2983.6 r0 top value=2.49k
R113 "ERJ-2GE0R00X" 0402L 493.11,3066.83 r90 top value=0
R114 "CRCW02010000Z0ED" 0201L 436,450 r90 top value=0
R115 "CRCW02010000Z0ED" 0201L 749.22,1096.36 r180 top value=0
R116 "CRCW04020000Z0EDHP" 0402L 2099,1997.13 r270 bottom value=0
R117 "ERJ-2GE0R00X" 0402L 603.35,2137.94 r90 top value=0
R118 "CRCW04022K49FKED" 0402L 661.43,2137.94 r90 top value=2.49k
R119 "CRCW12061M00JNEA" 1206L 408.52,3123.81 r180 bottom value=1.0Meg
R120 "ERJ-2RKF4700X" 0402L 524.61,2118.25 r180 top value=470
R121 "CRCW040233R2FKED" 0402L 3138.94,4192.91 r180 bottom value=33.2
R122 "CRCW040233R2FKED" 0402L 3138.94,4134.94 r180 bottom value=33.2
R123 "CRCW04021K00FKED" 0402L 1277.59,346.18 r270 bottom value=1.00k
R124 "CRCW04021K00FKED" 0402L 1346.93,346.18 r270 bottom value=1.00k
R125 "CRCW040210K0FKED" 0402L 2458,1919.87 r270 top value=10.0k
R126 "CRCW04021K00FKED" 0402L 1313.19,346.18 r270 bottom value=1.00k
R127 "CRCW04021K00FKED" 0402L 1381.51,346.18 r270 bottom value=1.00k
R128 "ERJ-2GE0R00X" 0402L 1853.15,330.88 r90 bottom value=0
R129 "ERJ-2GE0R00X" 0402L 1805.76,330.3 r90 bottom value=0
R130 "CRCW12061M00JNEA" 1206L 248.33,2030.64 r180 bottom value=1.0Meg
R131 "ERJ-2GE0R00X" 0402L 1480.75,4339.96 r180 bottom value=0
R132 "CRCW04022K49FKED" 0402L 1030.65,2955.6 r90 top value=2.49k
R133 "CRCW04021K00FKED" 0402L 1960.71,4265.88 r270 bottom value=1.00k
R134 "CRCW040249R9FKED" 0402L 1123.53,513.97 r180 bottom value=49.9
R135 "CRCW02010000Z0ED" 0201L 958.02,734 r0 bottom value=0
R136 "ERJ-2GE0R00X" 0402L 1950,611.54 r180 bottom value=0
R137 "CRCW04022K49FKED" 0402L 1030.65,2822.91 r90 top value=2.49k
R138 "CRCW02010000Z0ED" 0201L 925.46,874.89 r270 bottom value=0
R139 "CRCW04022K49FKED" 0402L 1227.43,2730.46 r180 bottom value=2.49k
R140 "CRCW04021K00FKED" 0402L 1950.58,769.02 r0 bottom value=1.00k
R141 "CRCW04022K49FKED" 0402L 1177,2955.81 r90 top value=2.49k
R142 "CRCW04022K49FKED" 0402L 1277.72,2824.25 r90 top value=2.49k
R143 "CRCW04022K49FKED" 0402L 1284.09,2711.25 r90 bottom value=2.49k
R144 "CRCW040233R2FKED" 0402L 741.44,4465.4 r180 bottom value=33.2
R145 "CRCW040233R2FKED" 0402L 900.95,4676.27 r90 bottom value=33.2
R146 "ERJ-2GE0R00X" 0402L 954.16,4676.24 r90 bottom value=0
R147 "CRCW040233R2FKED" 0402L 1006.27,4676.98 r90 bottom value=33.2
R148 "ERJ-2GE0R00X" 0402L 1106.89,4677.01 r90 bottom value=0
R149 "ERJ-2GE0R00X" 0402L 1162.89,4677.01 r90 bottom value=0
R150 "ERJ-2GE0R00X" 0402L 1215.81,4677.01 r90 bottom value=0
R151 "ERJ-2GE0R00X" 0402L 1480.12,4531.01 r0 bottom value=0
R152 "ERJ-2GE0R00X" 0402L 1125.5,1067.8 r0 bottom value=0
R153 "ERJ-2GE0R00X" 0402L 1480.12,4479.83 r0 bottom value=0
R154 "ERJ-2GEJ101X" 0402L 1278.34,1172.52 r90 bottom value=100
R155 "CRCW040210K0FKED" 0402L 1156.34,617.99 r90 bottom value=10.0k
R156 "CRCW04026K04FKED" 0402L 1977.97,4658.95 r180 bottom value=6.04k
R157 "CRCW040210K0FKED" 0402L 741.44,4270.79 r0 bottom value=10.0k
R158 "ERJ-2GE0R00X" 0402L 1478.98,4102.86 r0 bottom value=0
R159 "CRCW04021K00FKED" 0402L 323.96,4718.01 r270 top value=1.00k
R160 "CRCW02010000Z0ED" 0201L 925.46,824.85 r90 bottom value=0
R161 "MCT06030Z0000ZP500" 0603L 3060.96,1381.17 r180 bottom value=0
R162 "ERJ-2GE0R00X" 0402L 1217.86,3926.57 r270 bottom value=0
R163 "CRCW04021K00FKED" 0402L 741.44,4415.03 r0 bottom value=1.00k
R164 "CRCW02010000Z0ED" 0201L 914.44,957 r0 bottom value=0
R165 "CRCW02010000Z0ED" 0201L 2593.6,3251.25 r270 bottom value=0
R166 "ERJ-2GE0R00X" 0402L 1480.12,4200.6 r0 bottom value=0
R167 "CRCW02010000Z0ED" 0201L 914.44,929 r0 bottom value=0
R168 "ERJ-2GE0R00X" 0402L 943.33,3266.5 r270 bottom value=0
R169 "CRCW040233R2FKED" 0402L 1164.49,3926.57 r270 bottom value=33.2
R170 "CRCW040233R2FKED" 0402L 1111.12,3926.57 r270 bottom value=33.2
R171 "CRCW040233R2FKED" 0402L 1058.91,3926.57 r270 bottom value=33.2
R172 "CRCW040210K5FKED" 0402L 1977.97,4696.95 r0 bottom value=10.5k
R173 "CRCW04022K49FKED" 0402L 1413.21,2652.36 r90 bottom value=2.49k
R174 "CRCW040230K0FKED" 0402L 3000.5,1301 r0 bottom value=30.0k
R175 "MCT06030Z0000ZP500" 0603L 3030.45,1187.69 r0 bottom value=0
R176 "HCJ0603ZT0R00" FP-HCJ0603ZT0R00_0603-MFG 1861,3246.81 r0 bottom value=0
R177 "CRCW040210K0FKED" 0402L 900.67,3265.5 r270 bottom value=10.0k
R178 "CRCW040233R2FKED" 0402L 3178.31,4192.91 r0 bottom value=33.2
R179 "CRCW040233R2FKED" 0402L 1332.18,4421.89 r90 top value=33.2
R180 "ERJ-2GEJ511X" 0402L 1332.18,4530.43 r270 top value=510
R181 "ERJ-2GE0R00X" 0402L 1322.15,4177.23 r270 top value=0
R182 "CRCW08050000Z0EA" 0805L 1480.13,4617.01 r180 bottom value=0
R183 "CRCW0402100KFKED" 0402L 1780.35,4423.56 r0 bottom value=100k
R184 "CRCW040210K0FKED" 0402L 894.36,4110.54 r180 top value=10.0k
R185 "CRCW040210K0FKED" 0402L 858,3265.5 r90 bottom value=10.0k
R186 "ERJ-2GE0R00X" 0402L 1169,3148.81 r270 bottom value=0
R187 "CRCW040210K0FKED" 0402L 894.36,4164.3 r180 top value=10.0k
R188 "CRCW02010000Z0ED" 0201L 1281.93,1382.04 r270 top value=0
R189 "HCJ0603ZT0R00" FP-HCJ0603ZT0R00_0603-MFG 2114.86,3665.51 r90 bottom value=0
R190 "ERJ-2GE0R00X" 0402L 1006.97,3348.63 r270 top value=0
R191 "HCJ0805ZT0R00" FP-HCJ0805ZT0R00_0805-MFG 770.21,3243.02 r180 top value=0
R192 "HCJ0603ZT0R00" FP-HCJ0603ZT0R00_0603-MFG 2003.5,2407.81 r180 bottom value=0
R193 "HCJ0603ZT0R00" FP-HCJ0603ZT0R00_0603-MFG 2003.5,2472 r180 bottom value=0
R194 "CRCW04024K87FKED" 0402L 1417.54,345.58 r90 bottom value=4.87k
R195 "CRCW040233R2FKED" 0402L 1434.01,2860.81 r180 top value=33.2
R196 "CRCW02010000Z0ED" 0201L 716.86,1927.9 r90 bottom value=0
R197 "CRCW02010000Z0ED" 0201L 370.69,450 r90 top value=0
R198 "CRCW02010000Z0ED" 0201L 403.34,450 r90 top value=0
R199 "CRCW04020000Z0EDHP" 0402L 2099,1997.13 r270 top value=0
R200 "HCJ0603ZT0R00" FP-HCJ0603ZT0R00_0603-MFG 2548.23,1551.06 r180 bottom value=0
R201 "CRCW040210K0FKED" 0402L 894.36,4006.75 r0 top value=10.0k
R202 "CRCW040249K9FKED" 0402L 1780.35,4603.23 r0 bottom value=49.9k
R203 "CRCW040229K4FKED" 0402L 1780.35,4550.19 r0 bottom value=29.4k
R204 "CRCW0402200KFKED" 0402L 1780.35,4473.42 r180 bottom value=200k
R205 "CRCW04022K20JNED" 0402L 894.36,4063.55 r0 top value=2.2k
R206 "CRCW08050000Z0EA" 0805L 261.15,4219.15 r270 bottom value=0
R207 "CRCW08050000Z0EA" 0805L 363.17,4218.32 r270 bottom value=0
R208 "CRCW040230K0FKED" 0402L 378.25,4381.16 r180 bottom value=30.0k
R209 "ERJ-2GE0R00X" 0402L 104.25,4142.83 r90 top value=0
R211 "CRCW04025K76FKED" 0402L 1394.64,2903.81 r180 top value=5.76k
R215 "CRCW02010000Z0ED" 0201L 262,900.81 r0 top value=0
R216 "CRCW02010000Z0ED" 0201L 2561.9,3251.25 r270 bottom value=0
R217 "RC0201JR-0710RL" 0201L 2613.94,3406.99 r90 bottom value=10
R218 "CRCW02010000Z0ED" 0201L 2900.69,3251.25 r270 bottom value=0
R219 "CRCW02010000Z0ED" 0201L 2361.24,3251.25 r270 bottom value=0
R220 "CRCW02010000Z0ED" 0201L 2833.94,3251.25 r270 bottom value=0
R221 "RC0201JR-0710RL" 0201L 2327.86,3251.25 r90 bottom value=10
R222 "CRCW040210K0FKED" 0402L 1559.7,1716.46 r180 bottom value=10.0k
R223 "CRCW02010000Z0ED" 0201L 1352.45,1490.31 r0 top value=0
R224 "CRCW02010000Z0ED" 0201L 2116,3284.98 r270 bottom value=0
R225 "CRCW040233R2FKED" 0402L 3178.31,4134.94 r0 bottom value=33.2
R226 "CRCW02010000Z0ED" 0201L 472.98,1457.42 r0 top value=0
R227 "RC0201JR-0710RL" 0201L 2145,3284.98 r90 bottom value=10
R228 "RC0201JR-0710RL" 0201L 2498.5,3251.25 r90 bottom value=10
R229 "CRCW02010000Z0ED" 0201L 2764.1,3251.25 r270 bottom value=0
R230 "CRCW040233R2FKED" 0402L 3178.31,4076.97 r0 bottom value=33.2
R231 "RC0201JR-0710RL" 0201L 2731.39,3251.25 r90 bottom value=10
R232 "RC0201JR-0710RL" 0201L 2912,3398.33 r90 bottom value=10
R233 "ERJ-2GE0R00X" 0402L 2697,3262.7 r270 bottom value=0
R234 "CRCW040233R2FKED" 0402L 1472.09,2577.02 r0 top value=33.2
R235 "RC0201JR-0710RL" 0201L 2626,3251.25 r90 bottom value=10
R236 "RC0201JR-0710RL" 0201L 2776,3398.33 r90 bottom value=10
R237 "CRCW040233R2FKED" 0402L 1472.4,2631.31 r0 top value=33.2
R238 "CRCW040233R2FKED" 0402L 1471.67,2676.6 r0 top value=33.2
R239 "CRCW040233R2FKED" 0402L 1473.12,2724.89 r0 top value=33.2
R240 "CRCW040233R2FKED" 0402L 1473.38,2773.09 r0 top value=33.2
R241 "ERJ-2GE0R00X" 0402L 986,3266.81 r270 bottom value=0
R242 "ERJ-2GEJ101X" 0402L 1148.99,3170.64 r180 bottom value=100
R243 "CRCW02014K70FKED" 0201_033L 740.29,1405.09 r0 bottom value=4.70k
R244 "ERJ-1GNJ220C" 0201L 292.66,1427.81 r0 bottom value=22
R245 "CRCW040233R2FKED" 0402L 1473.38,2860.81 r0 top value=33.2
R246 "ERJ-2GE0R00X" 0402L 1189.36,3128.27 r0 bottom value=0
R247 "CRCW040233R2FKED" 0402L 1171.49,2280.8 r270 top value=33.2
R248 "CRCW06031M00FKEA" 0603L 1008.66,3149.13 r270 bottom value=1.00Meg
R249 "CRCW040233R2FKED" 0402L 1116.04,2280.8 r270 top value=33.2
R251 "CRCW040210K0FKED" 0402L 1190,3382.5 r90 top value=10.0k
R252 "CRCW04022K49FKED" 0402L 1401.29,3360.05 r90 top value=2.49k
R253 "CRCW04022K49FKED" 0402L 1407.02,3360.97 r90 bottom value=2.49k
R254 "CRCW04022K49FKED" 0402L 1474.75,3360.05 r90 top value=2.49k
R255 "CRCW04022K49FKED" 0402L 1630.02,3056.06 r0 top value=2.49k
R256 "CRCW04022K49FKED" 0402L 1630.02,3103.94 r0 top value=2.49k
R257 "CRCW04022K49FKED" 0402L 1630.02,3151.97 r0 top value=2.49k
R258 "CRCW04022K49FKED" 0402L 1630.07,3236.99 r0 top value=2.49k
R260 "CRCW040226R7FKED" 0402L 1377.98,3618.51 r0 bottom value=26.7
R261 "ERJ-2GEJ511X" 0402L 1729.69,4114.73 r270 top value=510
R262 "ERJ-2GEJ511X" 0402L 2076.38,2119.41 r270 top value=510
R263 "ERJ-2GEJ511X" 0402L 242.79,1822.86 r180 top value=510
R264 "CRCW040210K0FKED" 0402L 144.45,1296.65 r270 top value=10.0k
R265 "CRCW04020000Z0EDHP" 0402L 1416.18,3586.4 r180 bottom value=0
R266 "ERJ-2GEJ511X" 0402L 49.46,1736.94 r90 top value=510
R267 "CRCW040210R0JNED" 0402L 185.16,1385.97 r270 top value=10
R268 "CRCW040210R2FKED" 0402L 64.98,1207.31 r90 top value=10.2
R269 "ERJ-2GE0R00X" 0402L 2114.86,3736.19 r90 bottom value=0
R270 "CRCW04020000Z0EDHP" 0402L 1416.18,3554.12 r180 bottom value=0
R271 "CRCW040210K0FKED" 0402L 2810,3398.33 r270 bottom value=10.0k
R272 "CRCW040210K0FKED" 0402L 2846,3398.33 r270 bottom value=10.0k
R273 "CRCW040210K0FKED" 0402L 2163.69,4371 r180 bottom value=10.0k
R274 "CRCW040226R7FKED" 0402L 1377.98,3522.02 r180 bottom value=26.7
R275 "ERJ-P06F1001V" 0805L 634.18,3525.09 r0 top value=1.00k
R276 "CRCW04022K94FKED" 0402L 2001.32,1212 r180 top value=2.94k
R277 "CRCW04022K94FKED" 0402L 2001.32,1291 r180 top value=2.94k
R278 "CRCW0402100KFKED" 0402L 1518.35,4047.24 r0 bottom value=100k
R279 "CRCW0402100KFKED" 0402L 2742,3398.33 r270 bottom value=100k
R280 "CRCW04022K20JNED" 0402L 1192.71,2181.7 r0 bottom value=2.2k
R281 "ERJ-P06F1001V" 0805L 634.18,3615.44 r0 top value=1.00k
R282 "CRCW0805100KJNEA" 0805_HV 489.23,3615.44 r0 top value=100k
R283 "CRCW040210K0FKED" 0402L 1300.63,1623.71 r90 top value=10.0k
R284 "CRCW0402330KFKED" 0402L 1948.63,1061.91 r0 bottom value=330k
R285 "CRCW0402330KFKED" 0402L 1948.63,989.49 r180 bottom value=330k
R286 "CRCW04022K49FKED" 0402L 1414.48,2747.54 r90 bottom value=2.49k
R287 "CRCW04022K49FKED" 0402L 1487,2612.99 r90 bottom value=2.49k
R288 "CRCW04022K49FKED" 0402L 1492.8,2747.54 r270 bottom value=2.49k
R289 "CRCW04022K49FKED" 0402L 1485.69,2903.81 r180 top value=2.49k
R290 "CRCW040233R2FKED" 0402L 1432.72,2577.02 r180 top value=33.2
R291 "ERJ-2GE0R00X" 0402L 2622.69,2224.81 r0 bottom value=0
R293 "CRCW060348K7FKEA" 0603L 870.42,2904.77 r270 top value=48.7k
R294 "CRCW060345K3FKEA" 0603L 927.83,2904.77 r90 top value=45.3k
R295 "ERJ-2GE0R00X" 0402L 907.18,3019.03 r90 top value=0
R296 "CRCW040210K0FKED" 0402L 1744.21,725.22 r0 top value=10.0k
R298 "CRCW0402750RFKED" 0402L 2173.8,473.41 r270 top value=750
R299 "CRCW040210K0FKED" 0402L 2291.63,473.41 r90 top value=10.0k
R300 "CRCW04027K87FKED" 0402L 2209.53,473.41 r270 top value=7.87k
R301 "CRCW040210K0FKED" 0402L 2046.15,647.92 r0 bottom value=10.0k
R302 "CRCW040282K5FKED" 0402L 2252.26,473.41 r90 top value=82.5k
R303 "CRCW040210K0FKED" 0402L 2046.15,611.54 r180 bottom value=10.0k
R304 "CRCW0402750RFKED" 0402L 2171.6,693.23 r270 top value=750
R305 "CRCW040210K0FKED" 0402L 2134.62,693.23 r90 top value=10.0k
R306 "CRCW04027K87FKED" 0402L 2209.53,693.23 r270 top value=7.87k
R307 "CRCW040282K5FKED" 0402L 2246.93,693.23 r90 top value=82.5k
R308 "CRCW0402750RFKED" 0402L 2172.54,919.85 r270 top value=750
R309 "CRCW040210K0FKED" 0402L 1901,330.88 r90 bottom value=10.0k
R310 "CRCW040210K0FKED" 0402L 2135.56,919.85 r90 top value=10.0k
R311 "CRCW04027K87FKED" 0402L 2209.53,919.85 r270 top value=7.87k
R312 "CRCW040210K0FKED" 0402L 1948,330.88 r270 bottom value=10.0k
R313 "CRCW040282K5FKED" 0402L 2245.64,919.85 r90 top value=82.5k
R315 "CRCW04021K00FKED" 0402L 1864.43,4008.97 r180 bottom value=1.00k
R316 "ERJ-2GE0R00X" 0402L 2023.75,4596.13 r90 bottom value=0
R317 "CRCW02010000Z0ED" 0201L 1755.08,1718.43 r180 bottom value=0
R318 "CRCW02010000Z0ED" 0201L 1559.7,1653.97 r0 bottom value=0
R319 "CRCW02010000Z0ED" 0201L 1754.64,1632.28 r0 bottom value=0
R320 "CRCW02010000Z0ED" 0201L 749.22,1174.67 r180 top value=0
R321 "CRCW02010000Z0ED" 0201L 244.45,1514.71 r0 bottom value=0
R322 "CRCW02010000Z0ED" 0201L 914.44,863.87 r0 bottom value=0
R323 "CRCW02010000Z0ED" 0201L 914.44,835.87 r0 bottom value=0
R324 "CRCW02010000Z0ED" 0201L 262,869.81 r0 top value=0
R325 "CRCW040233R2FKED" 0402L 1433.03,2631.31 r180 top value=33.2
R326 "CRCW040210K0FKED" 0402L 732,1147.81 r0 bottom value=10.0k
R327 "CRCW02010000Z0ED" 0201L 914.44,957 r0 top value=0
R328 "CRCW02010000Z0ED" 0201L 262.36,838.88 r0 top value=0
R329 "CRCW02010000Z0ED" 0201L 262.36,800.66 r0 top value=0
R330 "ERJ-2GE0R00X" 0402L 1480.13,4152.19 r0 bottom value=0
R331 "CRCW04021K00FKED" 0402L 3035.7,993.33 r270 top value=1.00k
R333 "ERJ-2GEJ101X" 0402L 78.84,1807.13 r0 top value=100
R334 "CRCW02010000Z0ED" 0201L 215.95,1867.45 r90 top value=0
R335 "CRCW040210K0FKED" 0402L 179.39,1871.76 r270 top value=10.0k
R336 "CRCW040233R2FKED" 0402L 1432.3,2676.6 r180 top value=33.2
R337 "CRCW040211K0FKED" 0402L 925.03,2418.89 r180 top value=11.0k
R338 "CRCW040233R2FKED" 0402L 1433.75,2724.89 r180 top value=33.2
R339 "CRCW040233R2FKED" 0402L 1434.01,2773.09 r180 top value=33.2
R340 "CRCW04022K20JNED" 0402L 1087.72,2955.53 r90 top value=2.2k
R341 "CRCW02010000Z0ED" 0201L 914.44,929 r0 top value=0
R342 "CRCW04022K20JNED" 0402L 1143.2,2955.53 r90 top value=2.2k
R344 "CRCW02010000Z0ED" 0201L 1052.75,2323.17 r90 top value=0
R345 "CRCW02010000Z0ED" 0201L 914.44,863.87 r0 top value=0
R346 "CSNL1206FT1L00" 1206L 2113.62,1788.99 r0 bottom value=0.001
R347 "ERJ-2GEJ511X" 0402L 2290,4558.32 r270 bottom value=510
R348 "CRCW040210R2FKED" 0402L 2093.62,1697.67 r270 bottom value=10.2
R349 "CRCW02010000Z0ED" 0201L 914.44,835.87 r0 top value=0
R350 "CRCW040210K0FKED" 0402L 1161.75,3187.4 r180 top value=10.0k
R351 "CRCW02010000Z0ED" 0201L 958.02,762 r0 top value=0
R352 "CRCW040210R2FKED" 0402L 2133.62,1697.67 r270 bottom value=10.2
R353 "ERJ-2GE0R00X" 0402L 1553.23,768.21 r270 top value=0
R354 "ERJ-2GE0R00X" 0402L 1477.16,668.58 r0 top value=0
R355 "ERJ-2GE0R00X" 0402L 1477.16,627.37 r0 top value=0
R356 "ERJ-2GE0R00X" 0402L 1477.16,586.58 r0 top value=0
R357 "ERJ-2GE0R00X" 0402L 1744.21,582.99 r180 top value=0
R358 "ERJ-2GE0R00X" 0402L 1744.21,535.58 r180 top value=0
R359 "ERJ-2GE0R00X" 0402L 1744.21,677.81 r180 top value=0
R360 "ERJ-2GE0R00X" 0402L 1744.21,630.4 r180 top value=0
R361 "CRCW02010000Z0ED" 0201L 958.02,734 r0 top value=0
R362 "CRCW040210R2FKED" 0402L 1586.86,4152.19 r0 bottom value=10.2
R363 "CRCW02010000Z0ED" 0201L 958.02,689.06 r0 top value=0
R364 "CRCW02010000Z0ED" 0201L 958.02,661.06 r0 top value=0
R365 "CRCW02010000Z0ED" 0201L 958.02,630 r0 top value=0
R366 "CRCW02010000Z0ED" 0201L 958.02,602 r0 top value=0
R369 "CRCW040233R2FKED" 0402L 1116.04,2320.17 r270 top value=33.2
R370 "CRCW02010000Z0ED" 0201L 1016.02,2323.17 r90 top value=0
R371 "CRCW02010000Z0ED" 0201L 2880,3398.33 r270 bottom value=0
R374 "ERJ-1GNF33R2C" FP-ERJ-1GNF33R2C_0201-MFG 739.11,1359.57 r180 bottom value=33.2
R375 "ERJ-1GNF33R2C" FP-ERJ-1GNF33R2C_0201-MFG 292.66,1346.03 r180 bottom value=33.2
R376 "ERJ-1GNF33R2C" FP-ERJ-1GNF33R2C_0201-MFG 292.66,1388.1 r180 bottom value=33.2
R377 "ERJ-1GNF33R2C" FP-ERJ-1GNF33R2C_0201-MFG 1157.3,1430.27 r0 top value=33.2
R379 "CRCW02010000Z0ED" 0201L 262.36,764.55 r0 top value=0
R380 "CRCW040233R2FKED" 0402L 1963.32,4427 r0 bottom value=33.2
R381 "CRCW040233R2FKED" 0402L 1963.32,4535 r0 bottom value=33.2
R386 "CRCW040233R2FKED" 0402L 2464,3264.7 r90 bottom value=33.2
R387 "CRCW040233R2FKED" 0402L 1756.38,330.3 r90 bottom value=33.2
R388 "CRCW040233R2FKED" 0402L 1704.82,330.88 r90 bottom value=33.2
R389 "CRCW040233R2FKED" 0402L 1654.05,331.47 r90 bottom value=33.2
R390 "CRCW02010000Z0ED" 0201L 263.62,732.43 r0 top value=0
R391 "CRCW02010000Z0ED" 0201L 262.34,690.95 r0 top value=0
R399 "CRCW02010000Z0ED" 0201L 1157.3,1519.02 r180 top value=0
R400 "ERJ-2GE0R00X" 0402L 790.52,2327.93 r0 bottom value=0
R401 "ERJ-2GE0R00X" 0402L 360.63,2122.19 r180 bottom value=0
R409 "CRCW040210K0FKED" 0402L 361.36,4718.01 r90 top value=10.0k
R413 "CRCW040233R2FKED" 0402L 1171.49,2320.17 r270 top value=33.2
R414 "CRCW06031M00FKEAC" FP-CRCW06031M00FKEAC_0603-MFG 1034.2,2249.27 r180 top value=1M
R416 "CRCW040210K0FKED" 0402L 1032.2,4620.96 r180 top value=10.0k
R417 "CRCW040210K0FKED" 0402L 1032.2,4672.69 r0 top value=10.0k
R418 "CRCW040210K0FKED" 0402L 268.02,1119.56 r180 top value=10.0k
R419 "ERJ-2GE0R00X" 0402L 403.86,3009.18 r90 bottom value=0
R422 "CRCW02010000Z0ED" 0201L 265.9,1082.03 r0 top value=0
R423 "CRCW02010000Z0ED" 0201L 265.9,1050.53 r0 top value=0
R424 "CRCW02010000Z0ED" 0201L 747.25,1056 r0 top value=0
R425 "CRCW02010000Z0ED" 0201L 747.25,1017.19 r0 top value=0
R503 "CRCW0201100RFKED" 0201L 291.89,1297.35 r0 bottom value=100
